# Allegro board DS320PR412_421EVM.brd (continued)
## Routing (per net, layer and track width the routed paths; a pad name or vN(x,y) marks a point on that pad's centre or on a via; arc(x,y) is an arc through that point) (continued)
VCC0: length 2.2
  TOP w0.254: v1(103.05,18.72) 103.05,18.72 103.05,19.37 102.96,19.45 U1.13
  TOP w0.279: U1.5 v1(98.97,19.25)
VCC1: length 2.3
  TOP w0.254: U2.13 122.01,19.37 122.07,19.32 122.07,19.26 122.1,19.23 v1(122.1,18.64)
  TOP w0.279: U2.5 v1(118.02,19.25)
VCC2: length 2.7
  TOP w0.254: U3.13 64.86,19.45 64.95,19.37 64.95,19.33 64.98,19.3 v1(64.98,18.74)
  TOP w0.279: U3.5 v1(60.87,18.74)
VCC3: length 2.2
  TOP w0.254: v1(84.03,18.74) 84.03,19.3 84,19.33 84,19.37 83.91,19.45 U4.13
  TOP w0.279: U4.5 v1(79.92,19.25)
BP: length 10.2
  TOP w0.127: R90.1 R87.1 R86.1 12.15,78.45 11.84,78.77 R85.1 11.84,81.28 12.65,82.09 C104.2 14.15,82.09 14.21,82.15 U6.31
CLKREQ: length 87.7
  TOP w0.127: v1(57.4,44.88) 57.75,45.23 R130.1 ; C83.1 58.86,10.96 58.62,10.73 P5.B12 ; R125.1 v1(59.44,85.73)
  TOP w0.229: C83.1 58.96,11.58
  TOP w0.241: 58.96,11.58 v1(58.96,12.41)
  L3_SIG w0.102: v1(59.44,85.73) 57.38,83.68 57.38,61.29 55.89,59.8 55.89,49.69 57.4,48.18 v1(57.4,44.88) 57.4,43.78 55.55,41.93 55.55,15.81 v1(58.96,12.41)
EQ0_ADDR_0: length 165.8
  TOP w0.127: v1(94.96,22.27) 95.6,22.27 95.82,22.04 U1.40
  L4_SIG w0.102: JMP1.1 JMP1.3 JMP1.5 JMP1.7 120.9,123.9 133.99,123.9 137.54,120.34 137.54,112.22 138.81,110.94 138.81,35.69 130.24,27.12 109.07,27.12 106.35,24.4 96.58,24.4 94.96,22.77 v1(94.96,22.27)
EQ0_ADDR_1: length 162.4
  TOP w0.127: v1(113.31,21.54) 113.31,21.89 113.6,22.17 114.95,22.17 115.08,22.04 U2.40
  L4_SIG w0.102: JMP4.1 JMP4.3 JMP4.5 JMP4.7 159.89,124.15 166.12,124.15 169.42,120.85 169.42,112.72 164.21,107.52 153.8,107.52 141.86,95.58 141.86,34.77 130.78,23.69 114.96,23.69 113.31,22.04 v1(113.31,21.54)
EQ0_ADDR_2: length 167.4
  TOP w0.127: U3.40 57.9,22.04 57.72,22.22 56.87,22.22 56.68,22.04 v1(56.18,22.04)
  TOP w0.241: 37.97,126.44 JMP9.5
  L4_SIG w0.102: v1(56.18,22.04) 55.06,22.04 52.29,24.8 52.29,41.12 50.9,42.51 50.9,50.54 55.17,54.81 55.17,57.98 52.75,60.4 52.75,87.01 51.86,87.91 51.86,90.2 54.46,92.8 54.46,101.27 56.77,103.58 64.64,103.58 75.06,113.99 75.06,121.36 73.15,123.27 43.05,123.27 JMP9.7 JMP9.5 JMP9.3 JMP9.1
EQ0_ADDR_3: length 193.1
  TOP w0.127: v1(74.48,21.56) 74.48,22.05 74.66,22.23 76.77,22.23 76.95,22.04 U4.40
  L4_SIG w0.102: JMP14.1 JMP14.5 79.12,126.44 81.66,123.9 103.63,123.9 106.3,121.23 106.3,113.77 99.42,106.88 85.41,106.88 71.44,92.91 63.03,92.91 58.41,88.29 58.41,58.63 60.01,57.03 60.01,51.83 59.17,50.98 59.17,42.94 55.21,38.98 55.21,25.56 56.18,24.59 71.95,24.59 74.48,22.06 v1(74.48,21.56)
EQ1_0: length 142.6
  TOP w0.127: U1.20 106.2,22.04 106.43,22.27 v1(106.43,22.55)
  L4_SIG w0.102: JMP2.1 JMP2.5 JMP2.7 132.7,126.44 138.56,120.59 138.56,112.72 139.45,111.83 139.45,35.57 130.36,26.48 109.85,26.48 106.43,23.06 v1(106.43,22.55)
EQ1_1: length 141.1
  TOP w0.127: U2.20 125.48,22.04 v1(126.11,22.67)
  L4_SIG w0.102: JMP5.1 JMP5.3 JMP5.5 JMP5.7 170.69,111.33 165.74,106.37 154.31,106.37 142.37,94.44 142.37,34.39 130.65,22.67 v1(126.11,22.67)
EQ1_2: length 164.9
  TOP w0.127: U3.20 68.1,22.04 68.33,22.27 v1(68.33,22.55)
  TOP w0.241: 52.96,126.44 53.21,126.44 ; JMP10.1 45.59,126.44
  L4_SIG w0.102: v1(68.33,22.55) 68.33,22.05 66.73,20.45 57.75,20.45 56.95,21.26 56.95,22.15 56.48,22.61 55.16,22.61 52.74,25.04 52.74,46.9 51.59,48.05 51.59,50.4 55.78,54.59 55.78,58.46 53.41,60.82 53.41,90.14 54.9,91.63 54.9,96.63 60.33,102.06 64.14,102.06 75.82,113.74 75.82,121.74 73.53,124.03 55.37,124.03 52.96,126.44 JMP10.5 JMP10.3 JMP10.1
EQ1_3: length 193.6
  TOP w0.127: v1(87.38,22.55) 87.38,22.27 87.15,22.04 U4.20
  L4_SIG w0.102: v1(87.38,22.55) 87.38,22.05 85.78,20.45 76.2,20.45 75.06,21.59 75.06,22.11 72.14,25.04 56.36,25.04 55.66,25.74 55.66,37.66 59.81,41.82 59.81,49.22 60.8,50.21 60.8,58.24 58.86,60.18 58.86,88.11 62.18,91.43 75.02,91.43 88.82,105.23 98.73,105.23 107.06,113.56 107.06,122.12 104.52,124.66 93.98,124.66 JMP15.7 JMP15.5 JMP15.3
  L4_SIG w0.241: JMP15.1 JMP15.3
GAIN_SDA_0: length 154.7
  TOP w0.127: U1.1 96.07,20.07 v1(95.68,19.68)
  L4_SIG w0.102: v1(95.68,19.68) 95.48,19.68 95.11,19.31 94.18,19.31 93.57,19.92 93.57,24.1 95.35,25.88 105.83,25.88 108.13,28.18 129.8,28.18 137.78,36.16 137.78,98.96 121.86,114.88 J23.9 J23.7 J23.5 J23.3 J23.1
GAIN_SDA_1: length 132.5
  TOP w0.127: v1(111.9,20.06) 113.29,20.06 113.3,20.07 U2.1
  L4_SIG w0.102: J25.9 J25.7 J25.3 J25.1 141.1,114.9 140.68,114.47 140.68,35.16 130.27,24.76 112.92,24.76 111.02,22.85 111.02,20.3 111.26,20.06 v1(111.9,20.06)
GAIN_SDA_2: length 116.6
  TOP w0.127: v1(57.23,19.68) 57.75,19.68 58.13,20.07 U3.1 ; J27.9 J27.7 J27.5 J27.3 J27.1
  L4_SIG w0.102: J27.1 47.37,97.5 50.01,94.85 50.01,86.19 49.79,85.97 49.79,61.64 54.01,57.42 54.01,54.98 49.66,50.62 49.66,46.52 48.81,45.67 48.81,42.93 51.4,40.34 51.4,23.96 55.68,19.68 v1(57.23,19.68)
GAIN_SDA_3: length 140.5
  TOP w0.127: v1(77.4,19.1) 77.92,19.62 U4.1 ; J29.9 J29.7 J29.5 J29.3 J29.1
  L4_SIG w0.102: J29.1 78.61,112.6 65.79,99.77 61.34,99.77 56.94,95.37 56.94,87.48 55.81,86.36 55.81,67.73 56.77,66.77 56.77,52.37 53.86,49.45 53.86,25.65 55.81,23.7 70,23.7 74.6,19.1 v1(77.4,19.1)
JTAG1: length 127.7
  TOP w0.127: P5.B9 v1(53.62,10.82)
  L4_SIG w0.102: J5.3 35.76,110.31 33.25,110.31 32.97,110.03 32.97,93.04 30.2,90.27 30.2,35.76 28.12,33.68 28.12,29.26 40.74,16.64 44.7,16.64 49.76,11.58 51.31,11.58 52.07,10.82 v1(53.62,10.82)
JTAG1_A: length 41.9
  TOP w0.127: J5.1 41.4,107.21 41.4,104.11 40.01,102.72 40.01,89.74 45.01,84.73 53.34,84.73 53.9,85.29 53.9,88.8 54.43,89.33 J15.B9
JTAG1_B: length 76.5
  TOP w0.127: J16.B9 v1(54.43,51.2)
  BOTTOM w0.127: v1(54.43,51.2) 54.43,53.67 56.9,56.13 56.9,78.49 53.42,81.97 53.42,89.13 52.48,90.07 42.24,90.07 35.59,96.72 35.59,102.62 33.17,105.03 33.17,107.26 J5.5
JTAG2: length 90.3
  L4_SIG w0.102: J6.3 30.66,74.12 30.66,35.2 28.6,33.15 28.6,29.6 41.03,17.17 44.98,17.17 v1(49.96,12.19)
  BOTTOM w0.127: P5.A5 49.62,10.1 50.06,10.54 50.06,12.09 v1(49.96,12.19)
JTAG2_A: length 29
  TOP w0.127: J15.A5 v1(50.43,96.14)
  L3_SIG w0.102: v1(50.43,96.14) 50.43,96.78 49.89,97.33 43.64,97.33 42.55,96.24 42.55,89.94 40.31,87.71 37.24,87.71 36.27,86.74 36.27,85.09 J6.1
JTAG2_B: length 36.1
  TOP w0.127: J16.A5 v1(50.43,58.62)
  BOTTOM w0.127: v1(50.43,58.62) 50.43,61.91 49.15,63.19 35.17,63.19 34.14,64.23 34.14,75.06 J6.5
JTAG3: length 78.3
  L4_SIG w0.102: v1(50.47,12.83) 45.54,17.75 41.46,17.75 29.08,30.13 29.08,32.61 31.19,34.72 31.19,62.97 J7.3
  BOTTOM w0.127: v1(50.47,12.83) 50.63,12.66 50.63,11.73 50.62,11.71 P5.A6
JTAG3_A: length 44.3
  TOP w0.127: J15.A6 v1(51.43,96.14)
  L3_SIG w0.102: J7.1 34.54,72.42 34.54,86.41 36.86,88.72 40.06,88.72 41.88,90.55 41.88,96.57 43.15,97.84 50.52,97.84 51.43,96.93 v1(51.43,96.14)
JTAG3_B: length 22
  TOP w0.127: J16.A6 v1(51.43,58.62)
  BOTTOM w0.127: v1(51.43,58.62) 51.43,62.69 50.34,63.78 38.1,63.78 J7.5
JTAG4: length 63.5
  L4_SIG w0.102: v1(51.28,10.67) 51.08,10.87 49.94,10.87 45.16,15.65 40.82,15.65 26.95,29.51 26.95,34.85 22,39.8 22,45.77 22.58,46.35 25.55,46.35 26.09,45.82 J8.3
  BOTTOM w0.127: P5.A7 51.62,5.7 51.94,6.02 51.94,6.5 51.46,6.98 51.46,10.49 v1(51.28,10.67)
JTAG4_A: length 74.8
  TOP w0.127: J15.A7 v1(52.43,96.18)
  L3_SIG w0.102: J8.1 33.93,49.63 33.93,87.05 36.45,89.56 39.6,89.56 41.05,91.01 41.05,96.9 42.55,98.4 51.61,98.4 52.43,97.58 v1(52.43,96.18)
JTAG4_B: length 35.2
  TOP w0.229: v1(52.12,55.42) 52.43,55.74 J16.A7
  BOTTOM w0.127: v1(52.12,55.42) 52.12,54.81 51.74,54.43 33.66,54.43 J8.5
JTAG5: length 57.6
  L4_SIG w0.102: v1(51.28,14.05) 50.67,14.05 46.18,18.54 42.75,18.54 38.48,22.81 38.48,31.9 32.08,38.3 32.08,45.69 32.51,46.12 32.77,46.13 34.36,46.13 J9.3
  BOTTOM w0.127: P5.A8 52.62,7.02 51.94,7.7 51.94,13.39 v1(51.28,14.05)
JTAG5_A: length 77
  TOP w0.127: J15.A8 v1(53.43,96.2)
  BOTTOM w0.127: v1(53.43,96.2) 53.43,94.42 58.06,89.79 58.06,84.05 59.16,82.96 59.16,59.69 61.37,57.48 61.37,53.47 58.62,50.72 58.62,45.29 57.61,44.27 J9.1
JTAG5_B: length 28.8
  TOP w0.127: J16.A8 v1(53.43,55.61)
  BOTTOM w0.127: J9.5 33.68,47.83 38.72,52.87 52.26,52.87 53.43,54.04 v1(53.43,55.61)
MODE: length 7.5
  TOP w0.127: U6.34 16.78,80.37 16.38,79.97 R89.1 16.36,78.38 15.72,77.74 15.72,76.46 15.46,76.2 14.84,76.2 13.76,77.29 R87.2
MODE_0: length 152.6
  TOP w0.127: U1.41 95.82,21.54 95.7,21.42 v1(95.67,21.42)
  TOP w0.241: JMP3.1 137.03,126.44
  L4_SIG w0.102: v1(95.67,21.42) 95.67,22.12 96.74,23.2 104.99,23.2 105.85,22.34 105.85,22.32 106.19,21.98 107.85,21.98 111.75,25.88 130.58,25.88 140.05,35.35 140.05,112.37 139.45,112.98 139.45,120.98 136.91,123.52 JMP3.1 JMP3.3 JMP3.5 JMP3.7
MODE_1: length 156.9
  TOP w0.127: U2.41 v1(114.73,21.54)
  L4_SIG w0.102: v1(114.73,21.54) 114.73,22.04 115.94,23.25 123.59,23.25 124.86,21.98 130.72,21.98 142.94,34.2 142.94,93.23 154.94,105.23 168.02,105.23 176.15,113.36 JMP6.1 JMP6.3 JMP6.5 JMP6.7
MODE_2: length 137.4
  TOP w0.127: U3.41 v1(57.58,21.54)
  L4_SIG w0.102: v1(57.58,21.54) 57.58,22.6 57.02,23.16 55.52,23.16 53.41,25.28 53.41,51.23 56.29,54.1 56.29,58.98 53.86,61.41 53.86,89.35 55.35,90.84 55.35,95.3 61.09,101.04 64.26,101.04 76.58,113.36 76.58,122.12 73.91,124.79 67.69,124.79 JMP11.7 JMP11.5 JMP11.3 JMP11.1
MODE_3: length 168.5
  TOP w0.127: U4.41 v1(76.63,21.54)
  L4_SIG w0.102: JMP16.1 JMP16.3 JMP16.5 JMP16.7 107.95,123.77 107.95,113.33 98.58,103.96 88.93,103.96 75.62,90.65 62.03,90.65 60.5,89.12 60.5,60.13 61.39,59.24 61.39,42.05 57.6,38.26 57.6,27.91 56.1,26.4 56.1,25.92 56.54,25.48 73.2,25.48 76.63,22.04 v1(76.63,21.54)
PD_0: length 116.7
  TOP w0.127: v1(106.25,21.04) U1.18
  L4_SIG w0.102: v1(161.67,96.53) 161.67,94.24 144.04,76.61 144.04,33.81 129.64,19.41 125.95,19.41 125.04,20.32 115.77,20.32 114.81,19.36 107.93,19.36 v1(106.25,21.04)
  BOTTOM w0.127: R35.2 v1(161.67,96.53)
PD_1: length 95.4
  TOP w0.127: v1(125.34,21.04) U2.18
  L4_SIG w0.102: v1(160.15,96.53) 160.15,93.73 143.48,77.07 143.48,33.99 129.41,19.91 126.47,19.91 v1(125.34,21.04)
  BOTTOM w0.127: R36.2 v1(160.15,96.53)
PD_2: length 157.9
  TOP w0.127: v1(68.22,21.04) U3.18
  L4_SIG w0.102: v1(68.22,21.04) 71.42,17.85 101.51,17.85 101.87,17.49 104.68,17.49 105.09,17.91 122.96,17.91 123.39,18.34 130.4,18.34 145.16,33.1 145.16,75.77 164.72,95.33 v1(164.72,96.53)
  BOTTOM w0.127: R37.2 v1(164.72,96.53)
PD_3: length 138
  TOP w0.127: v1(87.2,21.05) 87.18,21.05 87.18,21.04 U4.18
  L4_SIG w0.102: v1(163.19,96.53) 163.19,94.72 144.6,76.12 144.6,33.4 130.07,18.87 125.56,18.87 124.75,19.68 120.47,19.68 119.44,18.65 105.01,18.65 104.32,17.97 102.23,17.97 101.9,18.29 89.95,18.29 v1(87.2,21.05)
  BOTTOM w0.127: R38.2 v1(163.19,96.53)
PER0_N: length 61
  TOP w0.127: J16.A17 64.43,56.32 64.06,55.94 64.06,55.83 64.06,55.17 v1(64.29,54.94)
  L3_SIG w0.102: v1(64.29,54.94) 64.06,54.71 64.06,53.69 66.57,51.18 66.57,45.3 70.45,41.43 70.45,12.4 66.99,8.94 63.93,8.94 63.29,8.29 63.29,7.11 v1(63.51,6.88)
  BOTTOM w0.127: v1(63.51,6.88) 63.29,6.66 63.29,6.12 63.62,5.79 P5.A17
PER0_N_A: length 83.4
  TOP w0.127: U3.37 59.36,24.14 59.25,24.26 59.25,24.52 57.67,26.09 57.67,26.45 v1(57.89,26.67) ; J15.A17 64.43,96.96 64.07,96.59 64.07,95.8 v1(64.29,95.58)
  L3_SIG w0.102: v1(57.89,26.67) 57.66,26.9 57.66,33.36 57.84,33.54 58.76,33.54 59.08,33.87 59.08,34.33 58.76,34.66 57.84,34.66 57.66,34.84 57.66,35.09 57.84,35.27 58.76,35.27 59.08,35.59 59.08,36.06 58.76,36.38 57.84,36.38 57.66,36.56 57.66,39.06 59.55,40.95 59.55,54.23 58.81,54.97 58.81,57.5 64.48,63.17 64.48,95.03 64.11,95.39 64.11,95.4 v1(64.29,95.58)
PER0_P: length 61
  TOP w0.127: J16.A16 63.43,56.34 63.79,55.98 63.79,55.15 v1(63.58,54.94)
  L3_SIG w0.102: v1(62.8,6.88) 63.01,7.09 63.01,7.09 63.03,7.12 63.03,8.4 63.83,9.19 66.88,9.19 70.2,12.51 70.2,41.32 66.32,45.2 66.32,51.07 63.81,53.59 63.81,54.71 v1(63.58,54.94)
  BOTTOM w0.127: v1(62.8,6.88) 63.03,6.66 63.03,6.19 62.62,5.79 P5.A16
PER0_P_A: length 83.4
  TOP w0.127: U3.38 58.87,24.14 58.98,24.26 58.98,24.41 57.4,25.98 57.4,26.44 v1(57.18,26.67) ; v1(63.58,95.58) 63.8,95.8 63.8,96.61 63.43,96.98 J15.A16
  L3_SIG w0.102: v1(57.18,26.67) 57.41,26.9 57.41,33.47 57.74,33.79 58.65,33.79 58.83,33.97 58.83,34.22 58.65,34.4 57.74,34.4 57.41,34.73 57.41,35.19 57.74,35.52 58.65,35.52 58.83,35.7 58.83,35.95 58.65,36.13 57.74,36.13 57.41,36.46 57.41,39.17 59.29,41.06 59.29,54.12 58.55,54.86 58.55,57.6 64.23,63.28 64.23,94.92 63.78,95.36 63.78,95.37 v1(63.58,95.58)
PER1_N: length 61
  TOP w0.127: J16.A22 69.43,56.32 69.06,55.95 69.06,55.16 v1(69.29,54.94)
  L3_SIG w0.102: v1(68.51,6.88) 68.29,7.11 68.29,8.33 71.6,11.65 71.6,12.77 71.19,13.18 71.19,13.52 71.6,13.94 71.6,14.49 71.19,14.91 71.19,15.25 71.6,15.66 71.6,16.22 71.19,16.63 71.19,16.98 71.6,17.39 71.6,17.95 71.19,18.36 71.19,18.7 71.6,19.12 71.6,19.67 71.19,20.09 71.19,20.43 71.6,20.85 71.6,21.4 71.19,21.82 71.19,22.16 71.6,22.57 71.6,23.13 71.19,23.54 71.19,23.89 71.6,24.3 71.6,24.86 71.19,25.27 71.19,25.61 71.6,26.03 71.6,26.58 71.19,27 71.19,27.34 71.6,27.75 71.6,28.31 71.22,28.69 71.22,29.1 71.6,29.48 71.6,30.16 71.98,30.54 71.98,32.04 71.6,32.42 71.6,41.96 67.51,46.06 67.51,50.07 69.06,51.62 69.06,54.71 v1(69.29,54.94)
  BOTTOM w0.127: v1(68.51,6.88) 68.3,6.67 68.3,6.17 68.62,5.85 P5.A22
PER1_N_A: length 83.4
  TOP w0.127: v1(69.29,95.58) 69.07,95.8 69.07,96.59 69.43,96.96 J15.A22 ; U3.33 61.36,24.14 61.25,24.26 61.25,25.18 60.72,25.71 60.72,26.44 v1(60.94,26.67)
  L3_SIG w0.102: v1(69.29,95.58) 69.06,95.35 69.06,66.17 60.28,57.4 60.28,54.33 61.42,53.19 61.42,46.65 60.71,45.94 60.71,36.37 60.89,36.19 61.7,36.19 62.03,35.86 62.03,35.4 61.7,35.07 60.89,35.07 60.71,34.89 60.71,34.64 60.89,34.46 61.7,34.46 62.03,34.14 62.03,33.67 61.7,33.35 60.89,33.35 60.71,33.17 60.71,26.9 v1(60.94,26.67)
PER1_P: length 61
  TOP w0.127: J16.A21 68.43,56.34 68.78,55.99 68.78,55.14 v1(68.58,54.94)
  L3_SIG w0.102: v1(68.58,54.94) 68.81,54.71 68.81,51.73 67.25,50.18 67.25,45.95 71.35,41.86 71.35,32.32 71.73,31.93 71.73,30.65 71.35,30.27 71.35,29.59 70.93,29.17 70.93,28.62 71.35,28.2 71.35,27.86 70.93,27.45 70.93,26.89 71.35,26.48 71.35,26.13 70.93,25.72 70.93,25.16 71.35,24.75 71.35,24.41 70.93,23.99 70.93,23.44 71.35,23.02 71.35,22.68 70.93,22.26 70.93,21.71 71.35,21.3 71.35,20.95 70.93,20.54 70.93,19.98 71.35,19.57 71.35,19.22 70.93,18.81 70.93,18.26 71.35,17.84 71.35,17.5 70.93,17.08 70.93,16.53 71.35,16.11 71.35,15.77 70.93,15.36 70.93,14.8 71.35,14.39 71.35,14.04 70.93,13.63 70.93,13.07 71.35,12.66 71.35,11.75 68.03,8.44 68.03,7.12 68.01,7.09 68.01,7.09 v1(67.8,6.88)
  BOTTOM w0.127: v1(67.8,6.88) 68.03,6.66 68.03,6.2 67.62,5.79 P5.A21
PER1_P_A: length 83.4
  TOP w0.127: U3.34 60.87,24.14 60.98,24.26 60.98,25.07 60.45,25.6 60.45,26.44 v1(60.23,26.67) ; J15.A21 68.43,96.98 68.8,96.61 68.8,95.8 v1(68.58,95.58)
  L3_SIG w0.102: v1(60.23,26.67) 60.46,26.9 60.46,33.27 60.78,33.6 61.6,33.6 61.78,33.78 61.78,34.03 61.6,34.21 60.78,34.21 60.46,34.54 60.46,35 60.78,35.33 61.6,35.33 61.78,35.51 61.78,35.76 61.6,35.94 60.78,35.94 60.46,36.26 60.46,46.05 61.17,46.76 61.17,53.09 60.03,54.22 60.03,57.5 68.81,66.28 68.81,95.35 v1(68.58,95.58)
PER2_N: length 61.2
  TOP w0.127: v1(73.29,54.94) 73.04,55.18 73.04,55.92 73.43,56.31 J16.A26
  L3_SIG w0.102: v1(72.51,6.88) 72.29,7.11 72.29,9.03 73.05,9.8 73.05,12.72 72.73,13.05 72.56,13.05 72.38,13.23 72.38,13.48 72.56,13.66 72.73,13.66 73.05,13.99 73.05,14.45 72.73,14.78 72.56,14.78 72.38,14.96 72.38,15.21 72.56,15.39 72.73,15.39 73.05,15.71 73.05,16.18 72.73,16.5 72.56,16.5 72.38,16.68 72.38,16.93 72.56,17.11 72.73,17.11 73.05,17.44 73.05,17.9 72.73,18.23 72.56,18.23 72.38,18.41 72.38,18.66 72.56,18.84 72.73,18.84 73.05,19.17 73.05,19.63 72.73,19.96 72.56,19.96 72.38,20.14 72.38,20.39 72.56,20.57 72.73,20.57 73.05,20.89 73.05,21.36 72.73,21.69 72.56,21.69 72.38,21.86 72.38,22.12 72.56,22.29 72.73,22.29 73.05,22.62 73.05,23.09 72.73,23.41 72.56,23.41 72.38,23.59 72.38,23.84 72.56,24.02 72.73,24.02 73.05,24.35 73.05,42.33 71.34,44.04 71.34,45.09 72.11,45.85 72.11,46.82 71.34,47.59 71.34,50.17 73.06,51.89 73.06,54.71 v1(73.29,54.94)
  BOTTOM w0.127: P5.A26 72.62,5.86 72.29,6.19 72.29,6.66 v1(72.51,6.88)
PER2_N_A: length 83.3
  TOP w0.127: v1(63.97,26.67) 63.75,26.44 63.75,24.26 63.86,24.14 U3.28 ; J15.A26 73.43,96.96 73.07,96.59 73.07,95.8 v1(73.29,95.58)
  L3_SIG w0.102: v1(63.97,26.67) 63.74,26.9 63.74,32.92 63.92,33.1 64.29,33.1 64.62,33.42 64.62,33.89 64.29,34.21 63.92,34.21 63.74,34.39 63.74,34.65 63.92,34.82 64.29,34.82 64.62,35.15 64.62,35.61 64.29,35.94 63.92,35.94 63.74,36.12 63.74,45.21 62.16,46.8 62.16,53.49 62.16,53.49 62.16,53.5 61.02,54.63 61.02,56.66 73.38,69.02 73.38,95.13 73.11,95.39 73.11,95.4 v1(73.29,95.58)
PER2_P: length 61.2
  TOP w0.127: v1(72.58,54.94) 72.78,55.13 72.78,55.93 72.43,56.27 J16.A25
  L3_SIG w0.102: v1(71.8,6.88) 72.03,7.11 72.03,9.14 72.8,9.9 72.8,12.62 72.62,12.8 72.45,12.8 72.13,13.12 72.13,13.59 72.45,13.91 72.62,13.91 72.8,14.09 72.8,14.34 72.62,14.52 72.45,14.52 72.13,14.85 72.13,15.31 72.45,15.64 72.62,15.64 72.8,15.82 72.8,16.07 72.62,16.25 72.45,16.25 72.13,16.58 72.13,17.04 72.45,17.37 72.62,17.37 72.8,17.55 72.8,17.8 72.62,17.98 72.45,17.98 72.13,18.3 72.13,18.77 72.45,19.09 72.62,19.09 72.8,19.27 72.8,19.53 72.62,19.7 72.45,19.7 72.13,20.03 72.13,20.49 72.45,20.82 72.62,20.82 72.8,21 72.8,21.25 72.62,21.43 72.45,21.43 72.13,21.76 72.13,22.22 72.45,22.55 72.62,22.55 72.8,22.73 72.8,22.98 72.62,23.16 72.45,23.16 72.13,23.49 72.13,23.95 72.45,24.28 72.62,24.28 72.8,24.45 72.8,42.23 71.09,43.93 71.09,45.19 71.86,45.96 71.86,46.71 71.09,47.48 71.09,50.28 72.81,51.99 72.81,54.71 v1(72.58,54.94)
  BOTTOM w0.127: P5.A25 71.62,5.79 72.03,6.19 72.03,6.66 v1(71.8,6.88)
PER2_P_A: length 83.4
  TOP w0.127: U3.29 63.37,24.14 63.48,24.26 63.48,26.44 v1(63.26,26.67) ; J15.A25 72.43,96.98 72.8,96.61 72.8,95.8 v1(72.58,95.58)
  L3_SIG w0.102: v1(63.26,26.67) 63.49,26.9 63.49,33.02 63.82,33.35 64.18,33.35 64.36,33.53 64.36,33.78 64.18,33.96 63.82,33.96 63.49,34.29 63.49,34.75 63.82,35.08 64.18,35.08 64.36,35.26 64.36,35.51 64.18,35.69 63.82,35.69 63.49,36.01 63.49,45.11 61.9,46.69 61.9,53.38 61.9,53.39 61.9,53.39 60.77,54.53 60.77,56.76 73.12,69.12 73.12,95.02 72.78,95.36 72.78,95.37 v1(72.58,95.58)
PER3_N: length 61
  TOP w0.127: J16.A30 77.43,56.33 77.04,55.93 77.04,55.18 v1(77.29,54.94)
  L3_SIG w0.102: v1(77.29,54.94) 77.06,54.71 77.06,53.71 75.18,51.83 75.18,47.98 73.97,46.76 73.97,45.3 73.33,44.67 73.33,43.78 73.97,43.15 73.97,21.65 73.97,21.65 73.97,19.81 74.79,18.99 74.79,18.5 74.47,18.17 73.97,18.17 73.79,18 73.79,17.74 73.97,17.56 74.47,17.56 74.79,17.24 74.79,16.77 74.47,16.45 73.97,16.45 73.79,16.27 73.79,16.02 73.97,15.84 74.47,15.84 74.79,15.51 74.79,15.05 74.47,14.72 73.97,14.72 73.79,14.54 73.79,14.29 73.97,14.11 74.47,14.11 74.79,13.78 74.79,13.34 74.26,12.81 74.26,11.14 76.29,9.12 76.29,7.11 v1(76.51,6.88)
  BOTTOM w0.127: v1(76.51,6.88) 76.29,6.66 76.29,6.21 76.62,5.88 P5.A30
PER3_N_A: length 83.5
  TOP w0.127: U3.24 65.86,24.14 65.75,24.26 65.75,24.55 66.8,25.6 66.8,26.44 v1(67.03,26.67) ; v1(77.29,95.58) 77.07,95.8 77.07,96.59 77.43,96.96 J15.A30
  L3_SIG w0.102: v1(67.03,26.67) 66.8,26.9 66.8,43.66 62.93,47.53 62.93,53.9 61.79,55.04 61.79,56.09 77.06,71.36 77.06,95.35 v1(77.29,95.58)
PER3_P: length 61
  TOP w0.127: v1(76.58,54.94) 76.77,55.13 76.77,55.94 76.43,56.28 J16.A29
  L3_SIG w0.102: v1(76.58,54.94) 76.81,54.71 76.81,53.82 74.92,51.94 74.92,48.08 73.71,46.87 73.71,45.41 73.08,44.77 73.08,43.68 73.71,43.04 73.71,19.71 74.54,18.88 74.54,18.61 74.36,18.43 73.86,18.43 73.53,18.1 73.53,17.64 73.86,17.31 74.36,17.31 74.54,17.13 74.54,16.88 74.36,16.7 73.86,16.7 73.53,16.37 73.53,15.91 73.86,15.58 74.36,15.58 74.54,15.41 74.54,15.15 74.36,14.97 73.86,14.97 73.53,14.65 73.53,14.18 73.86,13.86 74.36,13.86 74.54,13.68 74.54,13.45 74.01,12.92 74.01,11.03 76.03,9.01 76.03,7.12 76.01,7.09 76.01,7.09 v1(75.8,6.88)
  BOTTOM w0.127: v1(75.8,6.88) 76.03,6.66 76.03,6.23 75.62,5.82 P5.A29
PER3_P_A: length 83.5
  TOP w0.127: v1(76.58,95.58) 76.8,95.8 76.8,96.61 76.43,96.98 J15.A29 ; v1(66.31,26.67) 66.54,26.44 66.54,25.71 65.48,24.66 65.48,24.26 65.37,24.14 U3.25
  L3_SIG w0.102: v1(66.31,26.67) 66.54,26.9 66.54,43.56 62.67,47.43 62.67,53.8 61.53,54.94 61.53,56.2 76.81,71.47 76.81,95.35 v1(76.58,95.58)
PER4_N: length 59.9
  TOP w0.127: v1(83.29,54.94) 83.05,55.17 83.05,55.87 83.43,56.26 J16.A36
  L3_SIG w0.102: v1(82.51,6.88) 82.29,7.11 82.29,8.35 89.65,15.71 89.65,36.64 85.21,41.07 85.21,44.5 84.51,45.21 84.51,46.02 85.21,46.73 85.21,49.85 83.06,52 83.06,54.71 v1(83.29,54.94)
  BOTTOM w0.127: P5.A36 82.62,5.8 82.29,6.12 82.29,6.66 v1(82.51,6.88)
PER4_N_A: length 83.5
  TOP w0.127: U4.37 78.41,24.14 78.3,24.26 78.3,24.52 76.72,26.09 76.72,26.45 v1(76.94,26.67) ; v1(83.29,95.58) 83.07,95.8 83.07,96.59 83.43,96.96 J15.A36
  L3_SIG w0.102: v1(76.94,26.67) 76.71,26.9 76.71,49.09 79.18,51.55 79.18,60.29 83.06,64.17 83.06,79.53 82.73,79.86 81.57,79.86 81.39,80.04 81.39,80.29 81.57,80.47 82.73,80.47 83.06,80.8 83.06,81.26 82.73,81.59 81.57,81.59 81.39,81.77 81.39,82.02 81.57,82.2 82.73,82.2 83.06,82.52 83.06,95.35 v1(83.29,95.58)
PER4_P: length 59.9
  TOP w0.127: J16.A35 82.43,56.25 82.79,55.9 82.79,55.14 v1(82.58,54.94)
  L3_SIG w0.102: v1(82.58,54.94) 82.81,54.71 82.81,51.89 84.96,49.74 84.96,46.84 84.25,46.13 84.25,45.1 84.96,44.4 84.96,40.97 89.39,36.53 89.39,15.81 82.03,8.45 82.03,7.12 82.01,7.09 82.01,7.09 v1(81.8,6.88)
  BOTTOM w0.127: P5.A35 81.62,5.79 82.03,6.19 82.03,6.66 v1(81.8,6.88)
PER4_P_A: length 83.5
  TOP w0.127: U4.38 77.92,24.14 78.03,24.26 78.03,24.41 76.45,25.98 76.45,26.44 v1(76.23,26.67) ; v1(82.58,95.58) 82.8,95.8 82.8,96.61 82.43,96.98 J15.A35
  L3_SIG w0.102: v1(76.23,26.67) 76.46,26.9 76.46,49.2 78.92,51.66 78.92,51.76 78.92,51.76 78.92,60.39 82.81,64.27 82.81,79.43 82.63,79.61 81.46,79.61 81.13,79.93 81.13,80.4 81.46,80.72 82.63,80.72 82.81,80.9 82.81,81.15 82.63,81.33 81.46,81.33 81.13,81.66 81.13,82.12 81.46,82.45 82.63,82.45 82.81,82.63 82.81,95.35 v1(82.58,95.58)
PER5_N: length 59.9
  TOP w0.127: v1(87.29,54.94) 87.07,55.15 87.07,55.93 87.43,56.29 J16.A40
  L3_SIG w0.102: v1(87.29,54.94) 87.06,54.71 87.06,53.62 88.69,51.99 88.69,46.3 88.16,45.77 88.16,44.75 88.69,44.22 88.69,39.97 90.8,37.86 90.8,25.53 91.3,25.03 91.3,24.56 90.8,24.06 90.8,23.8 91.3,23.31 91.3,22.83 90.8,22.34 90.8,22.07 91.3,21.58 91.3,21.1 90.8,20.61 90.8,20.35 91.3,19.85 91.3,19.38 90.8,18.88 90.8,18.62 91.3,18.12 91.3,17.65 90.8,17.16 90.8,16.89 91.3,16.4 91.3,15.92 90.8,15.43 90.8,14.87 86.29,10.35 86.29,7.11 v1(86.51,6.88)
  BOTTOM w0.127: v1(86.51,6.88) 86.29,6.66 86.29,6.16 86.62,5.83 P5.A40
PER5_N_A: length 83.5
  TOP w0.127: U4.33 80.41,24.14 80.3,24.26 80.3,25.18 79.77,25.71 79.77,26.44 v1(79.99,26.67) ; v1(87.29,95.58) 87.07,95.8 87.07,96.59 87.43,96.96 J15.A40
  L3_SIG w0.102: v1(87.29,95.58) 87.06,95.35 87.06,82.12 86.73,81.79 85.08,81.79 84.9,81.62 84.9,81.36 85.08,81.18 86.73,81.18 87.06,80.86 87.06,67.07 80.09,60.1 80.09,60.08 80.07,60.05 80.07,51.18 77.5,48.61 77.5,42.38 79.78,40.1 79.78,26.88 v1(79.99,26.67)
PER5_P: length 59.9
  TOP w0.127: v1(86.58,54.94) 86.8,55.16 86.8,55.92 86.43,56.29 J16.A39
  L3_SIG w0.102: v1(86.58,54.94) 86.81,54.71 86.81,53.51 88.43,51.89 88.43,46.4 87.91,45.88 87.91,44.64 88.43,44.12 88.43,39.86 90.55,37.75 90.55,25.42 91.04,24.93 91.04,24.66 90.55,24.17 90.55,23.7 91.04,23.2 91.04,22.94 90.55,22.44 90.55,21.97 91.04,21.47 91.04,21.21 90.55,20.71 90.55,20.24 91.04,19.75 91.04,19.48 90.55,18.99 90.55,18.51 91.04,18.02 91.04,17.76 90.55,17.26 90.55,16.79 91.04,16.29 91.04,16.03 90.55,15.53 90.55,14.97 86.03,10.46 86.03,7.11 v1(85.8,6.88)
  BOTTOM w0.127: P5.A39 85.62,5.74 86.03,6.14 86.03,6.66 v1(85.8,6.88)
PER5_P_A: length 83.5
  TOP w0.127: v1(86.58,95.58) 86.8,95.8 86.8,96.61 86.43,96.98 J15.A39 ; v1(79.28,26.67) 79.5,26.44 79.5,25.6 80.03,25.07 80.03,24.26 79.92,24.14 U4.34
  L3_SIG w0.102: v1(79.28,26.67) 79.53,26.92 79.53,39.99 77.24,42.28 77.24,48.72 79.81,51.29 79.81,51.39 79.81,60.15 79.84,60.18 79.84,60.21 86.81,67.18 86.81,80.75 86.63,80.93 84.98,80.93 84.65,81.26 84.65,81.72 84.98,82.05 86.63,82.05 86.81,82.23 86.81,95.35 v1(86.58,95.58)
PER6_N: length 59.8
  TOP w0.127: J16.A44 91.43,56.32 91.06,55.95 91.06,55.16 v1(91.29,54.94)
  L3_SIG w0.102: v1(91.29,54.94) 91.06,54.71 91.06,50.35 89.77,49.06 89.77,45.93 90.22,45.48 90.22,44.09 89.77,43.64 89.77,40.89 92.03,38.63 92.03,28.72 92.48,28.27 92.48,27.75 92.03,27.3 92.03,26.99 92.48,26.54 92.48,26.02 92.03,25.57 92.03,25.26 92.48,24.82 92.48,24.29 92.03,23.85 92.03,23.54 92.48,23.09 92.48,22.57 92.03,22.12 92.03,21.81 92.48,21.36 92.48,20.84 92.03,20.39 92.03,20.08 92.48,19.63 92.48,19.11 92.03,18.67 92.03,18.35 92.48,17.91 92.48,17.39 92.03,16.94 92.03,16.63 92.48,16.18 92.48,15.66 92.03,15.21 92.03,14.9 92.48,14.45 92.48,13.93 92.03,13.48 92.03,13.17 92.48,12.73 92.48,12.2 92.03,11.76 92.03,10.85 90.29,9.1 90.29,7.11 v1(90.51,6.88)
  BOTTOM w0.127: P5.A44 90.62,5.79 90.29,6.12 90.29,6.66 v1(90.51,6.88)
PER6_N_A: length 83.4
  TOP w0.127: v1(91.29,95.58) 91.07,95.8 91.07,96.6 91.43,96.97 J15.A44 ; v1(83.02,26.67) 82.8,26.44 82.8,24.26 82.91,24.14 U4.28
  L3_SIG w0.102: v1(83.02,26.67) 82.79,26.9 82.79,38.69 80.83,40.65 80.83,44.27 80.28,44.82 79.7,44.82 79.3,45.22 79.3,45.79 79.7,46.19 80.28,46.19 80.83,46.74 80.83,59.8 91.06,70.03 91.06,80.47 90.73,80.8 90.07,80.8 89.9,80.97 89.9,81.23 90.07,81.41 90.73,81.41 91.06,81.73 91.06,95.35 v1(91.29,95.58)
PER6_P: length 59.8
  TOP w0.127: v1(90.58,54.94) 90.79,55.15 90.79,55.94 90.43,56.3 J16.A43
  L3_SIG w0.102: v1(89.8,6.88) 90.03,7.11 90.03,9.21 91.78,10.95 91.78,11.86 92.22,12.31 92.22,12.62 91.78,13.07 91.78,13.59 92.22,14.04 92.22,14.35 91.78,14.79 91.78,15.32 92.22,15.76 92.22,16.08 91.78,16.52 91.78,17.04 92.22,17.49 92.22,17.8 91.78,18.25 91.78,18.77 92.22,19.22 92.22,19.53 91.78,19.98 91.78,20.5 92.22,20.95 92.22,21.26 91.78,21.7 91.78,22.23 92.22,22.67 92.22,22.98 91.78,23.43 91.78,23.95 92.22,24.4 92.22,24.71 91.78,25.16 91.78,25.68 92.22,26.13 92.22,26.44 91.78,26.89 91.78,27.41 92.22,27.85 92.22,28.17 91.78,28.61 91.78,38.53 89.52,40.79 89.52,43.75 89.97,44.2 89.97,45.37 89.52,45.82 89.52,49.17 90.81,50.46 90.81,54.71 v1(90.58,54.94)
  BOTTOM w0.127: v1(89.8,6.88) 90.03,6.66 90.03,6.1 89.62,5.7 P5.A43
PER6_P_A: length 83.4
  TOP w0.127: J15.A43 90.43,96.99 90.8,96.63 90.8,95.8 v1(90.58,95.58) ; U4.29 82.42,24.14 82.53,24.26 82.53,26.44 v1(82.31,26.67)
  L3_SIG w0.102: v1(82.31,26.67) 82.54,26.9 82.54,38.58 80.58,40.54 80.58,44.17 80.18,44.57 79.6,44.57 79.04,45.12 79.04,45.9 79.6,46.45 80.18,46.45 80.58,46.85 80.58,59.9 90.81,70.13 90.81,80.36 90.63,80.54 89.97,80.54 89.64,80.87 89.64,81.33 89.97,81.66 90.63,81.66 90.81,81.84 90.81,95.35 v1(90.58,95.58)
PER7_N: length 59.8
  TOP w0.127: J16.A48 95.43,56.24 95.11,55.91 95.11,55.12 v1(95.29,54.94)
  L3_SIG w0.102: v1(94.51,6.88) 94.29,7.11 94.29,8.68 93.22,9.75 93.22,15.15 93.39,15.33 93.77,15.33 94.09,15.65 94.09,16.12 93.77,16.45 93.39,16.45 93.22,16.62 93.22,16.88 93.39,17.05 93.77,17.05 94.09,17.38 94.09,17.85 93.77,18.17 93.39,18.17 93.22,18.35 93.22,24.81 96.04,27.64 96.04,36.2 95.4,36.84 95.4,37.72 96.04,38.36 96.04,41.47 93.41,44.1 93.41,48.77 95.06,50.42 95.06,54.71 v1(95.29,54.94)
  BOTTOM w0.127: P5.A48 94.62,5.79 94.29,6.12 94.29,6.66 v1(94.51,6.88)
PER7_N_A: length 83.4
  TOP w0.127: v1(86.08,26.67) 85.85,26.44 85.85,25.6 84.8,24.55 84.8,24.26 84.91,24.14 U4.24 ; v1(95.29,95.58) 95.07,95.8 95.07,96.59 95.43,96.96 J15.A48
  L3_SIG w0.102: v1(95.29,95.58) 95.06,95.35 95.06,70.19 81.57,56.7 81.57,46.83 81.97,46.43 82.02,46.43 82.58,45.88 82.58,45.1 82.02,44.55 81.97,44.55 81.57,44.15 81.57,41.76 85.85,37.48 85.85,26.9 v1(86.08,26.67)
PER7_P: length 59.9
  TOP w0.127: J16.A47 94.43,56.29 94.84,55.89 94.84,55.2 v1(94.58,54.94)
  L3_SIG w0.102: v1(94.58,54.94) 94.81,54.71 94.81,50.52 93.16,48.87 93.16,44 95.79,41.37 95.79,38.47 95.15,37.83 95.15,36.74 95.79,36.1 95.79,27.74 92.96,24.92 92.96,18.25 93.29,17.92 93.66,17.92 93.84,17.74 93.84,17.49 93.66,17.31 93.29,17.31 92.96,16.98 92.96,16.52 93.29,16.19 93.66,16.19 93.84,16.01 93.84,15.76 93.66,15.58 93.29,15.58 92.96,15.25 92.96,9.65 94.03,8.58 94.03,7.11 v1(93.8,6.88)
  BOTTOM w0.127: P5.A47 93.62,5.74 94.03,6.14 94.03,6.66 v1(93.8,6.88)
PER7_P_A: length 83.4
  TOP w0.127: J15.A47 94.43,96.98 94.8,96.61 94.8,95.8 v1(94.58,95.58) ; U4.25 84.42,24.14 84.53,24.26 84.53,24.66 85.59,25.71 85.59,26.44 v1(85.36,26.67)
  L3_SIG w0.102: v1(85.36,26.67) 85.59,26.9 85.59,37.37 81.31,41.65 81.31,44.26 81.86,44.81 81.92,44.81 82.32,45.21 82.32,45.78 81.92,46.18 81.86,46.18 81.31,46.73 81.31,56.8 94.81,70.3 94.81,95.35 v1(94.58,95.58)
PER8_N: length 54.8
  TOP w0.127: v1(60.17,14.51) 59.95,14.73 59.95,15.29 60.31,15.65 C45.1
  BOTTOM w0.127: v1(60.17,14.51) 59.95,14.29 59.95,10.25 61.64,8.56 87.95,8.56 88.33,8.18 88.33,7.95 88.56,7.73 88.87,7.73 89.09,7.95 89.09,8.18 89.47,8.56 90.01,8.56 90.39,8.18 90.39,7.95 90.61,7.73 90.93,7.73 91.15,7.95 91.15,8.18 91.53,8.56 92.07,8.56 92.45,8.18 92.45,7.95 92.67,7.73 92.99,7.73 93.21,7.95 93.21,8.18 93.59,8.56 94.12,8.56 94.5,8.18 94.5,7.95 94.73,7.73 95.04,7.73 95.27,7.95 95.27,8.18 95.65,8.56 96.18,8.56 96.56,8.18 96.56,7.95 96.78,7.73 97.1,7.73 97.32,7.95 97.32,8.18 97.7,8.56 98.71,8.56 99.29,7.99 99.29,6.16 99.62,5.83 P5.A53
PER8_N_B: length 70.8
  TOP w0.127: v1(100.29,54.94) 100.07,55.16 100.07,55.97 100.43,56.34 J16.A53 ; U3.35 60.36,24.14 60.25,24.26 60.25,24.66 59.19,25.71 59.19,27.33 v1(59.42,27.56)
  L4_SIG w0.102: v1(100.29,54.94) 100.06,54.71 100.06,50.55 96.75,47.24 70.65,47.24 65.39,41.99 65.39,41.73 65.96,41.17 65.96,40.7 65.63,40.37 65.17,40.37 64.6,40.94 64.35,40.94 64.17,40.76 64.17,40.51 64.74,39.94 64.74,39.48 64.41,39.15 63.95,39.15 63.38,39.72 63.13,39.72 59.19,35.78 59.19,27.78 v1(59.42,27.56)
PER8_P: length 54.9
  TOP w0.127: v1(59.46,14.51) 59.68,14.73 59.68,15.29 59.32,15.65 C44.1
  BOTTOM w0.127: v1(59.46,14.51) 59.68,14.29 59.68,10.14 61.53,8.29 87.84,8.29 88.07,8.07 88.07,7.84 88.44,7.46 88.98,7.46 89.36,7.84 89.36,8.07 89.58,8.29 89.9,8.29 90.12,8.07 90.12,7.84 90.5,7.46 91.04,7.46 91.42,7.84 91.42,8.07 91.64,8.29 91.96,8.29 92.18,8.07 92.18,7.84 92.56,7.46 93.1,7.46 93.48,7.84 93.48,8.07 93.7,8.29 94.01,8.29 94.24,8.07 94.24,7.84 94.62,7.46 95.15,7.46 95.53,7.84 95.53,8.07 95.76,8.29 96.07,8.29 96.29,8.07 96.29,7.84 96.67,7.46 97.21,7.46 97.59,7.84 97.59,8.07 97.81,8.29 98.6,8.29 99.02,7.88 99.02,6.15 98.62,5.75 P5.A52
PER8_P_B: length 70.8
  TOP w0.127: v1(99.58,54.94) 99.8,55.16 99.8,55.97 99.43,56.34 J16.A52 ; v1(58.7,27.56) 58.93,27.33 58.93,25.6 59.98,24.55 59.98,24.26 59.87,24.14 U3.36
  L4_SIG w0.102: v1(99.58,54.94) 99.81,54.71 99.81,50.66 96.65,47.5 70.54,47.5 65.14,42.09 65.14,41.63 65.71,41.06 65.71,40.81 65.53,40.63 65.27,40.63 64.71,41.2 64.24,41.2 63.91,40.87 63.91,40.41 64.48,39.84 64.48,39.59 64.3,39.41 64.05,39.41 63.48,39.97 63.02,39.97 58.93,35.89 58.93,27.78 v1(58.7,27.56)
PER9_N: length 54.6
  TOP w0.127: v1(62.2,13.62) 61.98,13.84 61.98,15.28 C47.1
  BOTTOM w0.127: v1(62.2,13.62) 61.98,13.4 61.98,11.2 63.91,9.27 100.31,9.27 100.69,8.89 100.69,7.76 100.92,7.53 101.23,7.53 101.45,7.76 101.45,8.89 101.83,9.27 102.73,9.27 103.28,8.72 103.28,6.17 103.62,5.83 P5.A57
PER9_N_B: length 70.8
  TOP w0.127: J16.A57 104.43,56.32 104.07,55.95 104.07,55.16 v1(104.29,54.94) ; U3.31 62.36,24.14 62.23,24.28 62.23,27.32 v1(62.47,27.56)
  L4_SIG w0.102: v1(62.47,27.56) 62.24,27.78 62.24,35.29 65.17,38.22 65.42,38.22 65.94,37.7 66.4,37.7 66.73,38.03 66.73,38.49 66.21,39.01 66.21,39.26 66.39,39.44 66.64,39.44 67.16,38.92 67.63,38.92 67.96,39.25 67.96,39.71 67.44,40.23 67.44,40.49 72.64,45.69 99.37,45.69 104.06,50.39 104.06,54.71 v1(104.29,54.94)
PER9_P: length 54.7
  TOP w0.127: v1(61.49,13.62) 61.72,13.84 61.72,15.28 C46.1
  BOTTOM w0.127: v1(61.49,13.62) 61.72,13.4 61.72,11.08 63.8,9 100.2,9 100.42,8.78 100.42,7.65 100.81,7.26 101.34,7.26 101.72,7.65 101.72,8.78 101.94,9 102.62,9 103.01,8.61 103.01,6.14 102.62,5.75 P5.A56
PER9_P_B: length 70.8
  TOP w0.127: v1(103.58,54.94) 103.8,55.16 103.8,55.97 103.43,56.34 J16.A56 ; U3.32 61.87,24.14 61.96,24.24 61.96,27.35 v1(61.76,27.56)
  L4_SIG w0.102: v1(61.76,27.56) 61.99,27.78 61.99,35.4 65.06,38.47 65.53,38.47 66.05,37.95 66.3,37.95 66.48,38.13 66.48,38.39 65.96,38.91 65.96,39.37 66.29,39.7 66.75,39.7 67.27,39.18 67.52,39.18 67.7,39.36 67.7,39.61 67.18,40.13 67.18,40.6 72.53,45.95 99.26,45.95 103.81,50.49 103.81,54.71 v1(103.58,54.94)
PER10_N: length 54.8
  TOP w0.127: v1(64.24,14.51) 64.01,14.73 64.01,15.28 C49.1
  BOTTOM w0.127: P5.A61 107.62,5.83 107.29,6.16 107.29,7.21 106.91,7.59 106.36,7.59 106.14,7.81 106.14,8.13 106.36,8.35 106.91,8.35 107.29,8.73 107.29,9.21 106.5,10.01 66.77,10.01 64.01,12.77 64.01,14.29 v1(64.24,14.51)
PER10_N_B: length 70.8
  TOP w0.127: v1(108.29,54.94) 108.07,55.16 108.07,55.95 108.43,56.32 J16.A61 ; U3.26 64.86,24.14 64.75,24.26 64.75,25.07 65.28,25.6 65.28,27.33 v1(65.5,27.56)
  L4_SIG w0.102: v1(108.29,54.94) 108.06,54.71 108.06,50.42 101.76,44.12 73.93,44.12 69.05,39.24 69.05,38.99 69.34,38.69 69.34,38.23 69.01,37.9 68.55,37.9 68.26,38.19 68,38.19 67.82,38.02 67.82,37.76 68.12,37.47 68.12,37.01 67.79,36.68 67.32,36.68 67.03,36.97 66.78,36.97 65.27,35.46 65.27,27.78 v1(65.5,27.56)
PER10_P: length 54.8
  TOP w0.127: v1(63.53,14.51) 63.75,14.73 63.75,15.28 C48.1
  BOTTOM w0.127: v1(63.53,14.51) 63.75,14.29 63.75,12.66 66.66,9.74 106.39,9.74 107.03,9.1 107.03,8.84 106.8,8.62 106.25,8.62 105.87,8.24 105.87,7.7 106.25,7.32 106.8,7.32 107.02,7.1 107.02,6.15 106.62,5.75 P5.A60
PER10_P_B: length 70.8
  TOP w0.127: U3.27 64.37,24.14 64.48,24.26 64.48,25.18 65.01,25.71 65.01,27.33 v1(64.79,27.56) ; J16.A60 107.43,56.34 107.8,55.97 107.8,55.16 v1(107.58,54.94)
  L4_SIG w0.102: v1(107.58,54.94) 107.81,54.71 107.81,50.53 101.65,44.37 73.82,44.37 68.79,39.34 68.79,38.88 69.08,38.59 69.08,38.34 68.9,38.16 68.65,38.16 68.36,38.45 67.9,38.45 67.57,38.12 67.57,37.66 67.86,37.37 67.86,37.11 67.68,36.93 67.43,36.93 67.14,37.23 66.67,37.23 65.02,35.57 65.02,27.78 v1(64.79,27.56)
PER11_N: length 54.7
  TOP w0.127: v1(66.27,13.62) 66.05,13.84 66.05,15.28 C52.1
  BOTTOM w0.127: v1(66.27,13.62) 66.05,13.4 66.05,12.82 68.07,10.79 108.99,10.79 111.3,8.48 111.3,6.15 111.62,5.83 P5.A65
PER11_N_B: length 70.8
  TOP w0.127: v1(112.29,54.94) 112.07,55.16 112.07,55.95 112.43,56.32 J16.A65 ; U3.22 66.86,24.02 66.75,24.13 66.75,24.25 68.33,25.83 68.33,27.33 v1(68.55,27.56)
  L4_SIG w0.102: v1(68.55,27.56) 68.32,27.78 68.32,35.76 69.39,36.83 69.65,36.83 69.83,36.64 70.29,36.64 70.62,36.97 70.62,37.44 70.44,37.62 70.44,37.87 75.11,42.54 104.11,42.54 112.06,50.49 112.06,54.71 v1(112.29,54.94)
PER11_P: length 54.8
  TOP w0.127: v1(65.56,13.62) 65.78,13.84 65.78,15.28 C51.1
  BOTTOM w0.127: P5.A64 110.62,5.75 111.04,6.17 111.04,8.37 108.88,10.53 67.96,10.53 65.78,12.71 65.78,13.4 v1(65.56,13.62)
PER11_P_B: length 70.8
  TOP w0.127: v1(111.58,54.94) 111.8,55.16 111.8,55.97 111.43,56.34 J16.A64 ; U3.23 66.37,24.02 66.48,24.14 66.48,24.36 68.06,25.94 68.06,27.34 v1(67.84,27.56)
  L4_SIG w0.102: v1(67.84,27.56) 68.07,27.78 68.07,35.86 69.29,37.08 69.75,37.08 69.94,36.9 70.19,36.9 70.37,37.08 70.37,37.33 70.18,37.52 70.18,37.98 75,42.8 104.01,42.8 111.81,50.6 111.81,54.71 v1(111.58,54.94)
PER12_N: length 52.5
  TOP w0.127: C55.1 79,15.28 79,14.73 v1(79.22,14.51)
  BOTTOM w0.127: v1(79.22,14.51) 79,14.29 79,13.95 81.5,11.44 90.6,11.44 91.78,12.62 114.56,12.62 115.29,11.89 115.29,10.76 114.91,10.38 114.07,10.38 113.84,10.16 113.84,9.84 114.07,9.62 114.91,9.62 115.29,9.24 115.29,8.71 114.91,8.33 114.07,8.33 113.84,8.1 113.84,7.79 114.07,7.56 114.91,7.56 115.27,7.21 115.27,6.11 115.62,5.75 P5.A69
PER12_N_B: length 66.2
  TOP w0.127: U4.35 79.41,24.14 79.3,24.26 79.3,24.66 78.24,25.71 78.24,27.33 v1(78.47,27.56) ; v1(116.29,54.94) 116.07,55.16 116.07,55.95 116.43,56.32 J16.A69
  L4_SIG w0.102: v1(116.29,54.94) 116.06,54.71 116.06,50.86 106.4,41.2 82.75,41.2 78.24,36.68 78.24,34.99 78.42,34.81 78.75,34.81 79.08,34.48 79.08,34.02 78.75,33.69 78.42,33.69 78.24,33.51 78.24,33.26 78.42,33.08 78.75,33.08 79.08,32.76 79.08,32.29 78.75,31.97 78.42,31.97 78.24,31.79 78.24,27.78 v1(78.47,27.56)
PER12_P: length 52.5
  TOP w0.127: v1(78.51,14.51) 78.73,14.73 78.73,15.28 C54.1
  BOTTOM w0.127: P5.A68 114.62,5.75 115,6.13 115,7.1 114.8,7.3 113.96,7.3 113.58,7.68 113.58,8.21 113.96,8.59 114.8,8.59 115.03,8.82 115.03,9.13 114.8,9.35 113.96,9.35 113.58,9.73 113.58,10.27 113.96,10.65 114.8,10.65 115.03,10.87 115.03,11.78 114.45,12.35 91.89,12.35 90.71,11.18 81.39,11.18 78.73,13.84 78.73,14.29 v1(78.51,14.51)
PER12_P_B: length 66.2
  TOP w0.127: U4.36 78.92,24.14 79.03,24.26 79.03,24.55 77.98,25.6 77.98,27.33 v1(77.75,27.56) ; v1(115.58,54.94) 115.8,55.16 115.8,55.97 115.43,56.34 J16.A68
  L4_SIG w0.102: v1(115.58,54.94) 115.81,54.71 115.81,50.96 106.3,41.45 82.65,41.45 77.98,36.79 77.98,34.88 78.31,34.56 78.64,34.56 78.82,34.38 78.82,34.12 78.64,33.95 78.31,33.95 77.98,33.62 77.98,33.16 78.31,32.83 78.64,32.83 78.82,32.65 78.82,32.4 78.64,32.22 78.31,32.22 77.98,31.89 77.98,27.78 v1(77.75,27.56)
PER13_N: length 52.4
  TOP w0.127: C57.1 81.03,15.28 81.03,14.73 v1(81.25,14.51)
  BOTTOM w0.127: v1(81.25,14.51) 81.03,14.29 81.03,14.03 82.89,12.18 89.79,12.18 91.19,13.58 117.04,13.58 119.29,11.33 119.29,9.44 118.91,9.06 117.9,9.06 117.68,8.84 117.68,8.52 117.9,8.3 118.91,8.3 119.25,7.96 119.25,6.12 119.62,5.75 P5.A73
PER13_N_B: length 66.2
  TOP w0.127: v1(81.52,27.56) 81.28,27.32 81.28,24.28 81.41,24.14 U4.31 ; J16.A73 120.43,56.32 120.07,55.95 120.07,55.16 v1(120.29,54.94)
  L4_SIG w0.102: v1(120.29,54.94) 120.06,54.71 120.06,50.77 109.15,39.85 85.04,39.85 81.29,36.1 81.29,34.9 81.47,34.72 81.76,34.72 82.09,34.39 82.09,33.93 81.76,33.6 81.47,33.6 81.29,33.42 81.29,33.17 81.47,32.99 81.76,32.99 82.09,32.66 82.09,32.2 81.76,31.87 81.47,31.87 81.29,31.7 81.29,27.78 v1(81.52,27.56)
PER13_P: length 52.4
  TOP w0.127: v1(80.54,14.51) 80.77,14.73 80.77,15.28 C56.1
  BOTTOM w0.127: P5.A72 118.62,5.75 118.99,6.12 118.99,7.85 118.8,8.03 117.79,8.03 117.41,8.41 117.41,8.95 117.79,9.33 118.8,9.33 119.03,9.55 119.03,11.22 116.93,13.31 91.3,13.31 89.9,11.91 82.78,11.91 80.77,13.92 80.77,14.29 v1(80.54,14.51)
PER13_P_B: length 66.2
  TOP w0.127: U4.32 80.92,24.14 81.01,24.24 81.01,27.35 v1(80.81,27.56) ; v1(119.58,54.94) 119.8,55.16 119.8,55.97 119.43,56.34 J16.A72
  L4_SIG w0.102: v1(80.81,27.56) 81.04,27.78 81.04,31.8 81.37,32.13 81.66,32.13 81.84,32.31 81.84,32.56 81.66,32.74 81.37,32.74 81.04,33.07 81.04,33.53 81.37,33.86 81.66,33.86 81.84,34.03 81.84,34.29 81.66,34.47 81.37,34.47 81.04,34.79 81.04,36.21 84.94,40.11 109.04,40.11 119.81,50.87 119.81,54.71 v1(119.58,54.94)
PER14_N: length 52.5
  TOP w0.127: v1(83.29,14.51) 83.06,14.73 83.06,15.28 C59.1
  BOTTOM w0.127: P5.A77 123.62,5.77 123.27,6.12 123.27,7.64 122.91,7.99 122.66,7.99 122.44,8.21 122.44,8.53 122.66,8.75 122.91,8.75 123.29,9.13 123.29,10.36 119.13,14.52 89.65,14.52 88.15,13.01 83.92,13.01 83.06,13.86 83.06,14.29 v1(83.29,14.51)
PER14_N_B: length 66.2
  TOP w0.127: v1(84.55,27.56) 84.33,27.33 84.33,25.6 83.8,25.07 83.8,24.26 83.91,24.14 U4.26 ; J16.A77 124.43,56.32 124.07,55.95 124.07,55.16 v1(124.29,54.94)
  L4_SIG w0.102: v1(124.29,54.94) 124.06,54.71 124.06,54.56 124.06,54.56 124.06,50.45 111.68,38.07 87.74,38.07 84.32,34.66 84.32,33.22 84.5,33.04 85.01,33.04 85.33,32.71 85.33,32.25 85.01,31.92 84.5,31.92 84.32,31.74 84.32,27.78 v1(84.55,27.56)
PER14_P: length 52.5
  TOP w0.127: C58.1 82.8,15.28 82.8,14.73 v1(82.58,14.51)
  BOTTOM w0.127: v1(82.58,14.51) 82.8,14.29 82.8,13.75 83.8,12.75 88.26,12.75 89.76,14.25 119.02,14.25 123.03,10.25 123.03,9.24 122.8,9.02 122.55,9.02 122.17,8.64 122.17,8.1 122.55,7.72 122.8,7.72 123,7.53 123,6.13 122.62,5.75 P5.A76
PER14_P_B: length 66.2
  TOP w0.127: J16.A76 123.43,56.34 123.8,55.97 123.8,55.16 v1(123.58,54.94) ; U4.27 83.42,24.14 83.53,24.26 83.53,25.18 84.06,25.71 84.06,27.33 v1(83.84,27.56)
  L4_SIG w0.102: v1(83.84,27.56) 84.07,27.78 84.07,31.85 84.4,32.17 84.9,32.17 85.08,32.35 85.08,32.6 84.9,32.78 84.4,32.78 84.07,33.11 84.07,34.77 87.63,38.33 111.58,38.33 123.81,50.56 123.81,54.46 123.81,54.46 123.81,54.71 v1(123.58,54.94)
PER15_N: length 52.5
  TOP w0.127: v1(85.32,14.51) 85.1,14.73 85.1,15.28 C62.1
  BOTTOM w0.127: P5.A81 127.62,5.83 127.28,6.17 127.28,8.43 120.16,15.55 89.24,15.55 87.47,13.79 85.18,13.79 85.1,13.87 85.1,14.3 v1(85.32,14.51)
PER15_N_B: length 66.1
  TOP w0.127: U4.22 85.91,24.02 85.8,24.13 85.8,24.25 87.38,25.83 87.38,27.33 v1(87.6,27.56) ; v1(128.29,54.94) 128.07,55.16 128.07,55.95 128.43,56.32 J16.A81
  L4_SIG w0.102: v1(87.6,27.56) 87.37,27.78 87.37,34.79 89.44,36.86 114.27,36.86 128.06,50.64 128.06,54.71 v1(128.29,54.94)
PER15_P: length 52.5
  TOP w0.127: C61.1 84.83,15.28 84.83,14.73 84.61,14.51 v1(84.61,14.51)
  BOTTOM w0.127: P5.A80 126.62,5.75 127.01,6.14 127.01,8.32 120.05,15.28 89.35,15.28 87.58,13.52 85.07,13.52 84.84,13.76 84.84,14.28 v1(84.61,14.51)
PER15_P_B: length 66.1
  TOP w0.127: v1(127.58,54.94) 127.8,55.16 127.8,55.97 127.43,56.34 J16.A80 ; v1(86.89,27.56) 87.11,27.34 87.11,25.94 85.53,24.36 85.53,24.14 85.42,24.02 U4.23
  L4_SIG w0.102: v1(127.58,54.94) 127.81,54.71 127.81,50.75 114.17,37.11 89.33,37.11 87.12,34.89 87.12,27.78 v1(86.89,27.56)
PERST#: length 128.2
  TOP w0.127: U7.10 v1(14.69,92.65)
  L4_SIG w0.102: v1(14.69,92.65) 14.69,87.92 13.82,87.05 13.82,76.28 14.96,75.13 21.34,75.13 22.02,74.45 22.02,63.98 22.61,63.4 24.33,63.4 J17.3 28.35,63.3 28.35,54.64 21.54,47.83 21.54,39.27 26.31,34.49 26.31,29.31 40.36,15.27 44.88,15.27 50.08,10.07 v1(55.59,10.07)
  BOTTOM w0.127: P5.A11 55.62,9.54 55.59,9.57 v1(55.59,10.07)
PERST#_A: length 67.6
  TOP w0.127: R121.2 v1(57.15,101.08)
  L3_SIG w0.102: v1(57.15,101.08) 55.61,102.62 35.87,102.62 31.89,98.64 31.89,80.99 21.73,70.83 21.73,65.6 21.98,65.35 J17.1
PERST#_B: length 38.8
  TOP w0.127: R128.2 56.43,61.58 v1(56.19,61.82)
  BOTTOM w0.127: v1(56.19,61.82) 54.48,61.82 53.19,60.53 53.19,58.82 51.19,56.82 31.8,56.82 28.91,59.72 28.91,65.28 J17.5
PERST_INV: length 179
  TOP w0.127: J22.2 176.53,104.22 169.9,110.85 27.18,110.85 18.9,102.56 18.9,97.94 18.34,97.38 14,97.38 13.39,96.78 U7.8
PET0_N: length 57.3
  TOP w0.127: P5.B15 61.62,5.79 61.26,6.15 61.26,6.4 61.89,7.02 61.89,11.42 62.87,12.4 67.79,12.4 71.06,15.68 71.06,28.86 62.05,37.87 62.05,40.81 61.33,41.54 61.33,42.37 62.05,43.09 62.05,48.23 62.43,48.62 J16.B15
PET0_N_A: length 149.8
  TOP w0.127: v1(94.23,30.11) 93.99,29.87 93.99,29.45 C4.2 ; v1(62.29,88.38) 62.07,88.6 62.07,89.42 62.43,89.79 J15.B15
  L4_SIG w0.102: v1(94.23,30.11) 94.01,30.33 94.01,34.24 95.43,35.66 127.45,35.66 132.71,40.92 132.71,56.09 125.53,63.27 84.98,63.27 62.06,86.18 62.06,88.15 v1(62.29,88.38)
PET0_P: length 57.3
  TOP w0.127: P5.B14 60.62,5.78 61,6.16 61,6.51 61.62,7.13 61.62,11.53 62.76,12.67 67.68,12.67 70.8,15.79 70.8,28.75 61.79,37.76 61.79,40.7 61.06,41.43 61.06,42.48 61.79,43.2 61.79,48.27 61.43,48.62 J16.B14
PET0_P_A: length 149.8
  TOP w0.127: v1(61.58,88.38) 61.8,88.6 61.8,89.41 61.43,89.78 J15.B14 ; C3.2 93.73,29.46 93.73,29.9 v1(93.52,30.11)
  L4_SIG w0.102: v1(93.52,30.11) 93.75,30.33 93.75,34.34 95.32,35.92 127.34,35.92 132.45,41.03 132.45,55.99 125.42,63.01 84.87,63.01 61.81,86.08 61.81,88.15 v1(61.58,88.38)
PET1_N: length 57.1
  TOP w0.127: J16.B20 67.43,48.64 67.06,48.26 67.06,47.58 67.07,47.57 67.07,46.89 66.5,46.32 65.78,46.32 65.37,45.91 65.37,45.33 65.78,44.93 66.5,44.93 67.07,44.36 67.07,43.56 66.5,43 65.78,43 65.37,42.59 65.37,42.01 65.78,41.6 66.5,41.6 67.07,41.03 67.07,40.23 66.5,39.67 65.78,39.67 65.37,39.26 65.37,38.68 65.78,38.27 66.5,38.27 67.07,37.71 67.07,34.92 71.95,30.04 71.95,11.96 66.29,6.3 66.29,6.12 66.62,5.79 P5.B20
PET1_N_A: length 150.6
  TOP w0.127: v1(98.3,30.11) 98.04,29.85 98.04,29.46 C8.2 ; v1(67.29,88.38) 67.07,88.6 67.07,89.39 67.43,89.76 J15.B20
  L4_SIG w0.102: v1(67.29,88.38) 67.06,88.15 67.06,87.42 89.38,65.1 127.39,65.1 134.11,58.38 134.11,39.66 128.51,34.06 115.12,34.06 114.8,34.39 114.8,34.75 114.62,34.92 114.37,34.92 114.19,34.75 114.19,34.39 113.86,34.06 113.4,34.06 113.07,34.39 113.07,34.75 112.89,34.92 112.64,34.92 112.46,34.75 112.46,34.39 112.13,34.06 111.67,34.06 111.34,34.39 111.34,34.75 111.16,34.92 110.91,34.92 110.73,34.75 110.73,34.39 110.4,34.06 109.94,34.06 109.61,34.39 109.61,34.75 109.44,34.92 109.18,34.92 109,34.75 109,34.39 108.68,34.06 108.21,34.06 107.89,34.39 107.89,34.75 107.71,34.92 107.46,34.92 107.28,34.75 107.28,34.39 106.95,34.06 106.49,34.06 106.16,34.39 106.16,34.75 105.98,34.92 105.73,34.92 105.55,34.75 105.55,34.39 105.22,34.06 99.8,34.06 98.07,32.33 98.07,30.33 v1(98.3,30.11)
PET1_P: length 57.2
  TOP w0.127: J16.B19 66.43,48.64 66.79,48.28 66.79,47.47 66.8,47.46 66.8,47 66.39,46.59 65.67,46.59 65.1,46.02 65.1,45.22 65.67,44.66 66.39,44.66 66.8,44.25 66.8,43.67 66.39,43.26 65.67,43.26 65.1,42.7 65.1,41.9 65.67,41.33 66.39,41.33 66.8,40.92 66.8,40.34 66.39,39.93 65.67,39.93 65.1,39.37 65.1,38.57 65.67,38 66.39,38 66.8,37.59 66.8,34.81 71.68,29.93 71.68,12.07 66.03,6.41 66.03,6.12 65.62,5.72 P5.B19
PET1_P_A: length 150.6
  TOP w0.127: J15.B19 66.43,89.78 66.8,89.41 66.8,88.6 v1(66.58,88.38) ; C7.2 97.78,29.45 97.78,29.92 v1(97.59,30.11)
  L4_SIG w0.102: v1(66.58,88.38) 66.81,88.15 66.81,87.32 89.28,64.85 127.28,64.85 133.85,58.27 133.85,39.76 128.4,34.32 115.23,34.32 115.05,34.49 115.05,34.85 114.72,35.18 114.26,35.18 113.93,34.85 113.93,34.49 113.75,34.32 113.5,34.32 113.32,34.49 113.32,34.85 113,35.18 112.53,35.18 112.21,34.85 112.21,34.49 112.03,34.32 111.77,34.32 111.6,34.49 111.6,34.85 111.27,35.18 110.81,35.18 110.48,34.85 110.48,34.49 110.3,34.32 110.05,34.32 109.87,34.49 109.87,34.85 109.54,35.18 109.08,35.18 108.75,34.85 108.75,34.49 108.57,34.32 108.32,34.32 108.14,34.49 108.14,34.85 107.81,35.18 107.35,35.18 107.02,34.85 107.02,34.49 106.85,34.32 106.59,34.32 106.41,34.49 106.41,34.85 106.09,35.18 105.62,35.18 105.3,34.85 105.3,34.49 105.12,34.32 99.69,34.32 97.82,32.44 97.82,30.33 v1(97.59,30.11)
PET2_N: length 57.4
  TOP w0.127: J16.B24 71.43,48.65 71.08,48.3 71.08,46.43 70.52,45.86 69.31,45.86 68.9,45.45 68.9,44.87 69.31,44.47 70.52,44.47 71.08,43.9 71.08,43.1 70.52,42.54 69.31,42.54 68.9,42.13 68.9,41.55 69.31,41.14 70.52,41.14 71.08,40.57 71.08,39.77 70.52,39.21 69.31,39.21 68.9,38.8 68.9,38.22 69.31,37.81 70.52,37.81 71.08,37.25 71.08,32.87 72.78,31.17 72.78,10.92 70.29,8.43 70.29,6.12 70.62,5.79 P5.B24
PET2_N_A: length 151.1
  TOP w0.127: v1(71.29,88.38) 71.07,88.6 71.07,89.38 71.43,89.75 J15.B24 ; C12.2 102.14,29.43 102.14,29.88 v1(102.36,30.11)
  L4_SIG w0.102: v1(102.36,30.11) 102.13,30.33 102.13,31.42 103.24,32.52 105.53,32.52 105.86,32.85 105.86,33.09 106.04,33.27 106.29,33.27 106.47,33.09 106.47,32.85 106.79,32.52 107.26,32.52 107.58,32.85 107.58,33.09 107.76,33.27 108.02,33.27 108.19,33.09 108.19,32.85 108.52,32.52 108.98,32.52 109.31,32.85 109.31,33.09 109.49,33.27 109.74,33.27 109.92,33.09 109.92,32.85 110.25,32.52 110.71,32.52 111.04,32.85 111.04,33.09 111.22,33.27 111.47,33.27 111.65,33.09 111.65,32.85 111.98,32.52 112.44,32.52 112.77,32.85 112.77,33.09 112.94,33.27 113.2,33.27 113.38,33.09 113.38,32.85 113.7,32.52 114.17,32.52 114.49,32.85 114.49,33.09 114.67,33.27 114.92,33.27 115.1,33.09 115.1,32.85 115.43,32.52 115.89,32.52 116.22,32.85 116.22,33.09 116.4,33.27 116.65,33.27 116.83,33.09 116.83,32.85 117.16,32.52 117.62,32.52 117.95,32.85 117.95,33.09 118.13,33.27 118.38,33.27 118.56,33.09 118.56,32.85 118.88,32.52 119.35,32.52 119.67,32.85 119.67,33.09 119.85,33.27 120.11,33.27 120.28,33.09 120.28,32.85 120.61,32.52 121.07,32.52 121.4,32.85 121.4,33.09 121.58,33.27 121.83,33.27 122.01,33.09 122.01,32.85 122.34,32.52 122.8,32.52 123.13,32.85 123.13,33.09 123.31,33.27 123.56,33.27 123.74,33.09 123.74,32.85 124.07,32.52 124.53,32.52 124.86,32.85 124.86,33.09 125.03,33.27 125.29,33.27 125.47,33.09 125.47,32.85 125.79,32.52 129.95,32.52 135.19,37.75 135.19,60.75 128.12,67.82 89.97,67.82 71.06,86.73 71.06,88.15 v1(71.29,88.38)
PET2_P: length 57.4
  TOP w0.127: J16.B23 70.43,48.64 70.82,48.26 70.82,46.54 70.41,46.13 69.2,46.13 68.63,45.56 68.63,44.76 69.2,44.2 70.41,44.2 70.82,43.79 70.82,43.21 70.41,42.8 69.2,42.8 68.63,42.24 68.63,41.44 69.2,40.87 70.41,40.87 70.82,40.46 70.82,39.88 70.41,39.47 69.2,39.47 68.63,38.91 68.63,38.11 69.2,37.54 70.41,37.54 70.82,37.13 70.82,32.76 72.52,31.06 72.52,11.03 70.03,8.54 70.03,6.12 69.62,5.72 P5.B23
PET2_P_A: length 151.2
  TOP w0.127: v1(101.65,30.11) 101.87,29.88 101.87,29.48 C11.2 ; J15.B23 70.43,89.78 70.8,89.41 70.8,88.6 v1(70.58,88.38)
  L4_SIG w0.102: v1(101.65,30.11) 101.88,30.33 101.88,31.52 103.13,32.77 105.42,32.77 105.6,32.95 105.6,33.2 105.93,33.52 106.39,33.52 106.72,33.2 106.72,32.95 106.9,32.77 107.15,32.77 107.33,32.95 107.33,33.2 107.66,33.52 108.12,33.52 108.45,33.2 108.45,32.95 108.63,32.77 108.88,32.77 109.06,32.95 109.06,33.2 109.38,33.52 109.85,33.52 110.17,33.2 110.17,32.95 110.35,32.77 110.61,32.77 110.78,32.95 110.78,33.2 111.11,33.52 111.57,33.52 111.9,33.2 111.9,32.95 112.08,32.77 112.33,32.77 112.51,32.95 112.51,33.2 112.84,33.52 113.3,33.52 113.63,33.2 113.63,32.95 113.81,32.77 114.06,32.77 114.24,32.95 114.24,33.2 114.57,33.52 115.03,33.52 115.36,33.2 115.36,32.95 115.53,32.77 115.79,32.77 115.97,32.95 115.97,33.2 116.29,33.52 116.76,33.52 117.08,33.2 117.08,32.95 117.26,32.77 117.51,32.77 117.69,32.95 117.69,33.2 118.02,33.52 118.48,33.52 118.81,33.2 118.81,32.95 118.99,32.77 119.24,32.77 119.42,32.95 119.42,33.2 119.75,33.52 120.21,33.52 120.54,33.2 120.54,32.95 120.72,32.77 120.97,32.77 121.15,32.95 121.15,33.2 121.47,33.52 121.94,33.52 122.27,33.2 122.27,32.95 122.44,32.77 122.7,32.77 122.87,32.95 122.87,33.2 123.2,33.52 123.67,33.52 123.99,33.2 123.99,32.95 124.17,32.77 124.42,32.77 124.6,32.95 124.6,33.2 124.93,33.52 125.39,33.52 125.72,33.2 125.72,32.95 125.9,32.77 129.85,32.77 134.93,37.86 134.93,60.65 128.02,67.56 89.87,67.56 70.81,86.62 70.81,88.15 v1(70.58,88.38)
PET3_N: length 57.4
  TOP w0.127: P5.B28 74.62,5.79 74.29,6.12 74.29,19.49 73.87,19.92 73.87,29.59 74.27,30 75.66,30 76.23,30.57 76.23,31.37 75.66,31.93 74.27,31.93 73.87,32.34 73.87,32.92 74.27,33.33 75.66,33.33 76.23,33.89 76.23,34.69 75.66,35.26 74.27,35.26 73.87,35.67 73.87,36.25 74.27,36.66 75.66,36.66 76.23,37.22 76.23,38.02 75.66,38.59 74.27,38.59 73.87,39 73.87,45.26 75.06,46.45 75.06,48.26 75.43,48.64 J16.B28
